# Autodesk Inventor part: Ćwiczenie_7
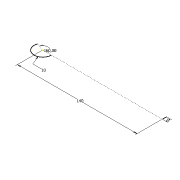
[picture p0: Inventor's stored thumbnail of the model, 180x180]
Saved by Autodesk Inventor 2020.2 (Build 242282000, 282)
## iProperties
Created: 2005-01
Part Number: Ćwiczenie_7
Document SubType Name: Modeling
Designer: F.Stasiak
Manufacturer: Standard
Standards Organization: Custom
Density: 1 g/cm^3
Material: Ogólny
Appearance: Domyślna
Manager: www.cadconsulting.pl
Company: Fabian Stasiak CAD Consulting
Author: F.Stasiak
Subject: Zbiór ćwiczeń. Autodesk Inventor 2020. Kurs podstawowy
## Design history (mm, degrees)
sketch "Szkic1"
  geometry: L1 (140, 5)-(140, 0); L2 (0, 0)-(140, 0); L3 (0, 0)-(-9.397, 3.42); A1 r 10 centre (0, 0) between (-9.397, 3.42) and (10, 0); 1 further point
  constraints: 6 end point, 2 point on circle, 1 centre point, 1 coincident, 1 horizontal, 1 point on line, 1 vertical
  dimensions: "d1" = 5 dimension on point (0, 0) L2.start A1 L1.start L1.end L1 L2 L3.end L3 A1.end; "d1" = 5 distance of L1.start L1.end; "d3" = 160 deg angle of L2 L3; "d20" = 140 distance of L2.start L1.end; "d21" = 10 radius of A1
node "Korpusy bryłowe"
node "Korpusy powierzchniowe"
